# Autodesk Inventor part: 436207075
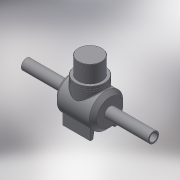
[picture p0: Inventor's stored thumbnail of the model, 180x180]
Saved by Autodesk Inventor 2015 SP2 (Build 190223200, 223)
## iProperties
Created: 2017-08
Part Number: 436207075
Material: Generic
Description: PLASSON PE BALL VALVE 75
Document SubType Name: Modeling
Designer: Кирилл
Density: 1 g/cm^3
Appearance: Default
Author: Кирилл
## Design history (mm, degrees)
derived "436207.ipt"
feature "Solid1::436207.ipt"
feature "Solid2::436207.ipt"
tag "TaggingFeature1"
body "Solid1"
other parameters: "d0" = 414, "d1" = 75, "d5" = 56.25, "d6" = 12.42, "d10" = 85, "d11" = 68, "d12" = 0.85, "d13" = 4, "d14" = 4, "d16" = 100 deg, "d17" = 48, "d18" = 9.6, "d20" = 87, "d21" = 0, "d22" = 0.85, "d26" = 8, "d28" = 0, "d29" = 1.7, "d_" = 75, "s_" = 8, "L_" = 414, "B_" = 87, "E_1" = 85
